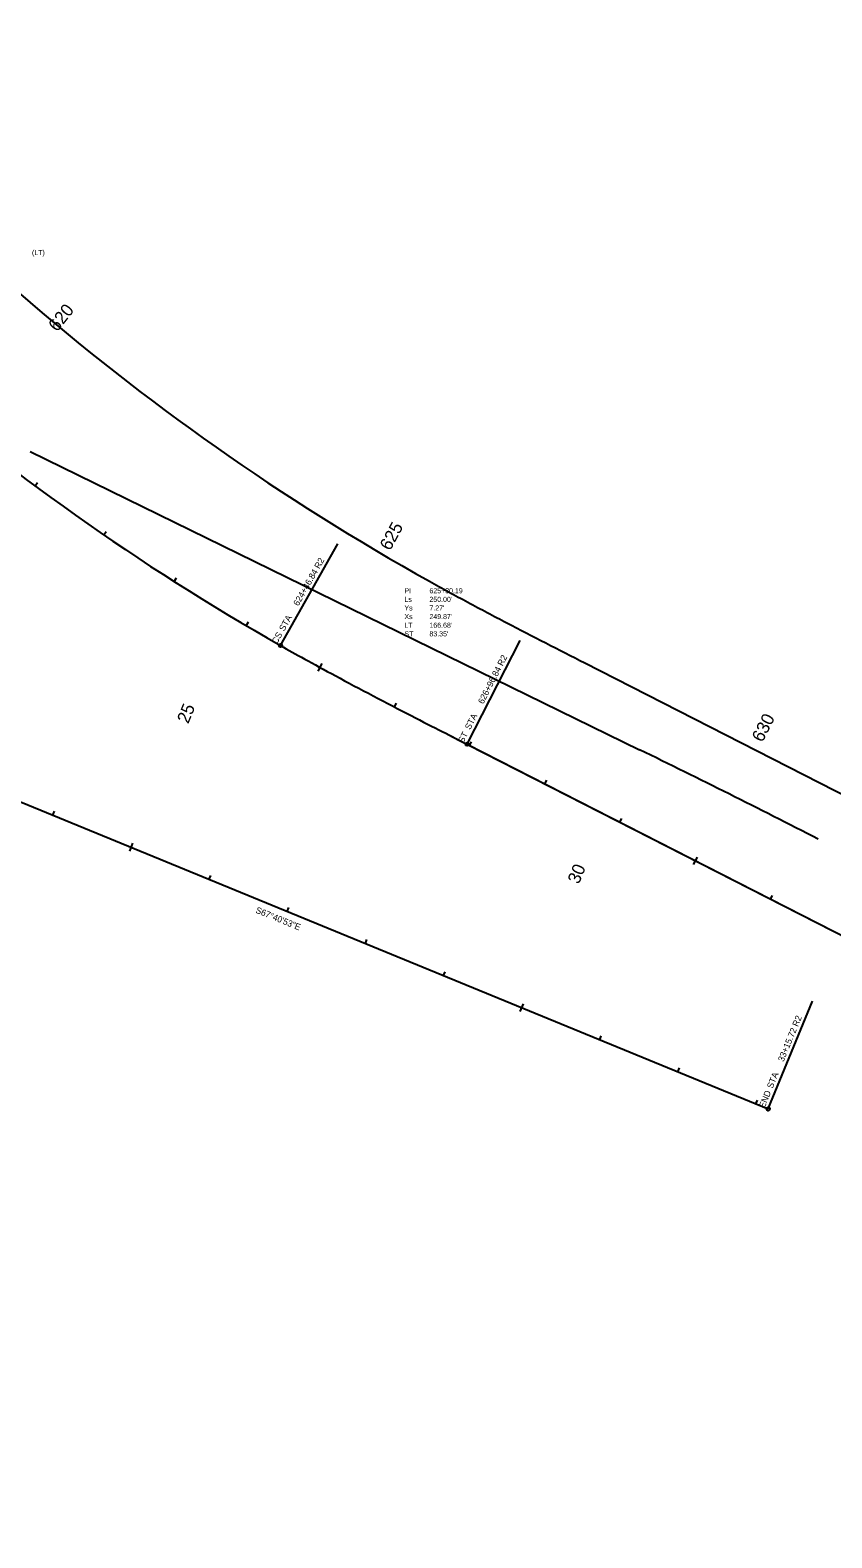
# Model space of a CAD drawing. Extents: x 1604882 to 1608571, y 865355 to 868094.
# Drawn here: x 1606055 to 1607005, y 865360 to 867144 of the extents above; entities that cross this region are included whole.
import ezdxf

# ---------------------------------------------------------------- set-up
doc = ezdxf.new("R2010")
doc.units = 0
for name, color, linetype in [('Default', 7, 'Continuous'), ('Modeling-Contours-Major-Existing', 7, 'Continuous'), ('Modeling-Contours-Minor-Existing', 7, 'Continuous'), ('Modeling-Flow Arrows-Existing', 7, 'Continuous'), ('Modeling-Low Points-Existing', 7, 'Continuous'), ('Modeling-Spot-Existing', 7, 'Continuous'), ('Modeling-Triangle Verticies-Existing', 7, 'Continuous'), ('Modeling-Triangles-Existing', 7, 'Continuous')]:
    doc.layers.add(name, color=color, linetype=linetype)

msp = doc.modelspace()

# ---------------------------------------------------------------- linework, layer by layer
at = {"layer": 'Default'}
for p, q in [((1606055.3, 866645.1), (1606776.9, 866292.2)), ((1606712.2, 866394.9), (1608570.8, 865446.1)), ((1605799.9, 866330.7), (1606929.3, 865867.1)), ((1606554, 866308.3), (1608412.4, 865359.6))]:
    msp.add_line(p, q, dxfattribs=at)
for centre, radius, start, end in [((1607922.2, 868994.2), 2864.6, 217.0392, 240.877), ((1607922.2, 868994.2), 2864.6, 217.0392, 240.877), ((1607764.2, 868907.8), 2864.6, 217.4592, 240.4569), ((1600714, 853895.4), 13800, 62.95704, 63.93823), ((1600714, 853895.4), 13800, 62.95704, 63.93823)]:
    msp.add_arc(centre, radius, start, end, dxfattribs=at)
for points in [[(1606528, 866491.7), (1606543.1, 866483.3), (1606573.6, 866466.7), (1606619.6, 866442.4), (1606665.8, 866418.6), (1606696.7, 866402.8), (1606712.1, 866394.9)], [(1606528, 866491.7), (1606543.1, 866483.3), (1606573.6, 866466.7), (1606619.6, 866442.4), (1606665.8, 866418.6), (1606696.7, 866402.8), (1606712.1, 866394.9)], [(1606351.8, 866415.6), (1606360.8, 866410.5), (1606379, 866400.3), (1606415.5, 866380.3), (1606461.5, 866355.9), (1606507.8, 866331.9), (1606544.9, 866312.9), (1606563.4, 866303.5), (1606572.7, 866298.7)]]:
    msp.add_open_spline(points, degree=3, dxfattribs=at)
at = {"layer": 'Modeling-Contours-Minor-Existing'}
for p, q in [((1606400.6, 866394.2), (1606395.8, 866385.4)), ((1606176.6, 866181.5), (1606172.8, 866172.3)), ((1606845, 866165.3), (1606840.5, 866156.4)), ((1606639.1, 865991.6), (1606635.3, 865982.4))]:
    msp.add_line(p, q, dxfattribs=at)
at = {"layer": 'Modeling-Spot-Existing'}
for p, q in [((1606351.8, 866415.6), (1606419.8, 866535.7)), ((1606419.8, 866535.7), (1606419.8, 866535.7)), ((1606572.7, 866298.7), (1606635.5, 866421.6)), ((1606635.5, 866421.6), (1606635.5, 866421.6)), ((1606929.3, 865867.1), (1606981.7, 865994.8)), ((1606981.7, 865994.8), (1606981.7, 865994.8))]:
    msp.add_line(p, q, dxfattribs=at)
for centre in [(1606351.8, 866415.6), (1606572.7, 866298.7), (1606929.3, 865867.1)]:
    msp.add_circle(centre, 1.98, dxfattribs=at)
at = {"layer": 'Modeling-Triangle Verticies-Existing'}
for p, q in [((1606061.1, 866604.5), (1606064.1, 866608.5)), ((1606142.5, 866546.4), (1606145.3, 866550.5)), ((1606225.9, 866491.3), (1606228.6, 866495.5)), ((1606311.2, 866439), (1606313.7, 866443.4)), ((1606486.6, 866343), (1606488.9, 866347.4)), ((1606575.5, 866297.3), (1606577.8, 866301.7)), ((1606664.6, 866251.8), (1606666.9, 866256.3)), ((1606082.2, 866214.9), (1606084.1, 866219.5)), ((1606753.7, 866206.4), (1606755.9, 866210.8)), ((1606267.2, 866138.9), (1606269.1, 866143.5)), ((1606931.8, 866115.4), (1606934.1, 866119.9)), ((1606359.7, 866100.9), (1606361.6, 866105.6)), ((1606452.2, 866063), (1606454.1, 866067.6)), ((1606544.7, 866025), (1606546.6, 866029.6)), ((1606729.7, 865949), (1606731.6, 865953.7)), ((1606822.2, 865911.1), (1606824.1, 865915.7)), ((1606914.7, 865873.1), (1606916.6, 865877.7))]:
    msp.add_line(p, q, dxfattribs=at)
at = {"layer": 'Modeling-Triangles-Existing'}
for p, q in [((1605799.9, 866330.7), (1606929.3, 865867.1)), ((1606572.7, 866298.7), (1608412.4, 865359.6))]:
    msp.add_line(p, q, dxfattribs=at)
msp.add_arc((1607764.2, 868907.8), 2864.6, 217.4592, 240.4569, dxfattribs=at)
msp.add_open_spline([(1606351.8, 866415.6), (1606360.8, 866410.5), (1606379, 866400.3), (1606415.5, 866380.3), (1606461.5, 866355.9), (1606507.8, 866331.9), (1606544.9, 866312.9), (1606563.4, 866303.5), (1606572.7, 866298.7)], degree=3, dxfattribs=at)

# ---------------------------------------------------------------- texts
at = {"layer": 'Modeling-Contours-Major-Existing'}
for s, rotation, p in [('620', 51.5194, (1606087.3, 866786)), ('625', 61.4071, (1606481.5, 866526.9)), ('25', 67.6814, (1606242.5, 866322.2)), ('630', 62.9571, (1606922.3, 866300.2)), ('30', 67.6814, (1606705, 866132.4))]:
    msp.add_text(s, height=15, rotation=rotation, dxfattribs=at).set_placement(p)
at = {"layer": 'Modeling-Flow Arrows-Existing'}
msp.add_text('S67°40\'53"E', height=7.5, rotation=337.6814, dxfattribs=at).set_placement((1606321.6, 866099.6))
at = {"layer": 'Modeling-Low Points-Existing'}
for s, p in [(' (LT)', (1606055.2, 866877.6)), ('PI   ', (1606498.5, 866477.4)), ('Ls   ', (1606498.5, 866467.2)), ('625+30.19', (1606528.1, 866477.4)), ("250.00'", (1606528.1, 866467.2)), ('Ys   ', (1606498.5, 866457)), ('Xs   ', (1606498.5, 866446.8)), ("7.27'", (1606528.1, 866457)), ("249.87'", (1606528.1, 866446.8)), ('ST   ', (1606498.5, 866426.4)), ('LT   ', (1606498.5, 866436.6)), ("83.35'", (1606528.1, 866426.4)), ("166.68'", (1606528.1, 866436.6))]:
    msp.add_text(s, height=6, dxfattribs=at).set_placement(p)
at = {"layer": 'Modeling-Spot-Existing'}
for s, rotation, p in [('624+46.84 R2', 60.4569, (1606372.9, 866461.7)), (' STA ', 60.4569, (1606354.7, 866429.5)), ('CS', 60.4569, (1606347.4, 866416.6)), ('626+96.84 R2', 62.9571, (1606591.8, 866345.7)), (' STA ', 62.9571, (1606575, 866312.8)), ('ST', 62.9571, (1606568.3, 866299.6)), ('33+15.72 R2', 67.6814, (1606947.3, 865922.4)), (' STA ', 67.6814, (1606933.2, 865888.1)), ('END', 67.6814, (1606924.8, 865867.6))]:
    msp.add_text(s, height=7.5, rotation=rotation, dxfattribs=at).set_placement(p)

doc.saveas('drawing.dxf')
